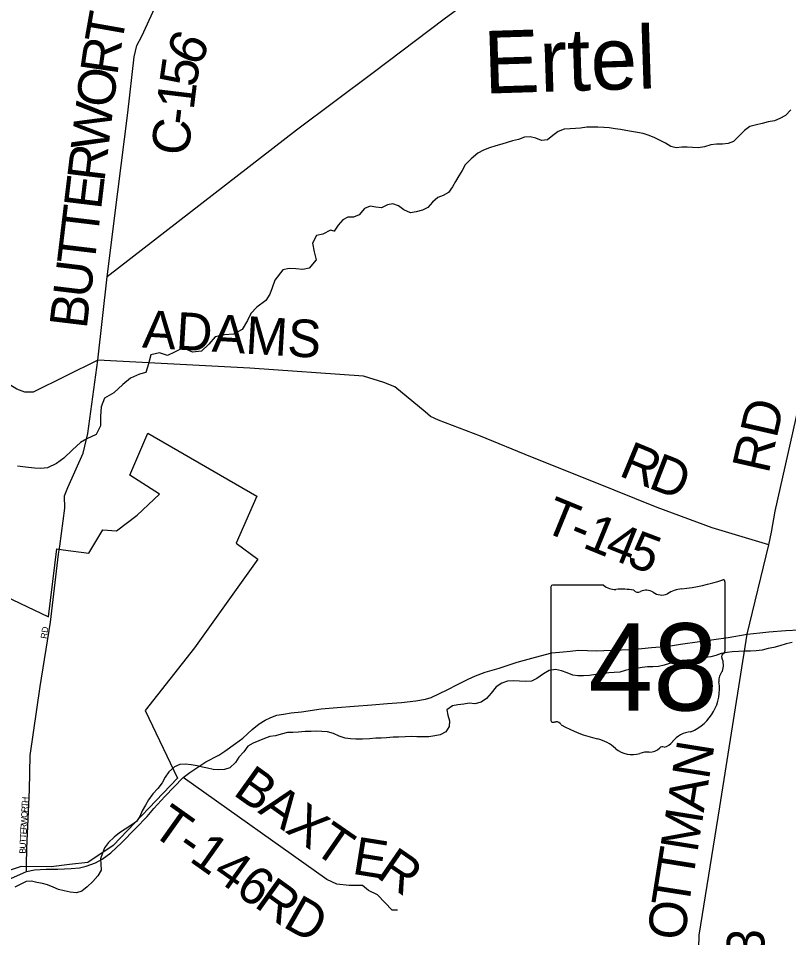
# Model space of a CAD drawing. Extents: x 0 to 1064, y 0 to 440.
# Drawn here: x 203.95 to 222.59, y 62.77 to 85.02 of the extents above; entities that cross this region are included whole.
import ezdxf

# ---------------------------------------------------------------- set-up
doc = ezdxf.new("R2010")
doc.units = 0
for name, color, linetype in [('GM_X_City_Street', 7, 'Continuous'), ('GM_X_City_Street_Text', 7, 'Continuous'), ('GM_X_Corporation', 7, 'Continuous'), ('GM_X_County_Road', 7, 'Continuous'), ('GM_X_County_Road_Text', 7, 'Continuous'), ('GM_X_Minor_River', 7, 'Continuous'), ('GM_X_Minor_River_Text', 7, 'Continuous'), ('GM_X_State_Location', 7, 'Continuous'), ('GM_X_State_Route', 7, 'Continuous'), ('GM_X_State_Shield', 7, 'Continuous'), ('GM_X_Township_Road', 7, 'Continuous'), ('GM_X_Township_Road_Text', 7, 'Continuous')]:
    doc.layers.add(name, color=color, linetype=linetype)

msp = doc.modelspace()

# ---------------------------------------------------------------- linework, layer by layer
at = {"layer": 'GM_X_City_Street'}
msp.add_lwpolyline([(204.15, 64.525), (204.154, 64.936), (204.221, 66.35), (204.236, 67.173), (204.474, 68.846), (204.731, 70.402), (204.924, 72.051), (204.949, 72.245)], dxfattribs=at)
at = {"layer": 'GM_X_Corporation'}
msp.add_lwpolyline([(201.73, 71.938), (204.68, 70.534), (204.882, 72.179), (205.035, 72.152), (205.655, 72.075), (205.997, 72.636), (206.326, 72.612), (206.826, 72.99), (207.362, 73.505), (206.643, 73.966), (207.082, 74.979), (209.718, 73.454), (209.218, 72.319), (209.742, 71.929), (208.211, 69.78), (207.021, 68.269), (207.798, 66.628), (206.247, 64.999), (205.631, 64.59), (205.188, 64.535), (204.746, 64.48), (204.02, 64.493), (203.4, 64.285)], dxfattribs=at)
at = {"layer": 'GM_X_County_Road'}
for points in [[(204.949, 72.245), (205.072, 73.161), (205.066, 73.464), (205.148, 73.663), (205.517, 74.495), (205.629, 74.973), (205.875, 76.746), (206.101, 78.761), (206.359, 80.822), (206.595, 82.732), (206.754, 84.084), (206.82, 84.362), (206.934, 84.591), (207.25, 85.272)], [(204.149, 64.367), (204.15, 64.525)]]:
    msp.add_lwpolyline(points, dxfattribs=at)
at = {"layer": 'GM_X_Minor_River'}
for points in [[(222.645, 82.806), (222.515, 82.669), (222.38, 82.592), (222.246, 82.539), (222.093, 82.511), (221.953, 82.477), (221.812, 82.443), (221.653, 82.397), (221.524, 82.308), (221.382, 82.164), (221.258, 82.039), (221.124, 81.986), (220.99, 81.976), (220.844, 81.972), (220.704, 81.956), (220.557, 81.91), (220.399, 81.888), (220.265, 81.89), (220.131, 81.898), (220.004, 81.901), (219.87, 81.884), (219.737, 81.917), (219.61, 81.998), (219.484, 82.061), (219.351, 82.124), (219.212, 82.18), (219.067, 82.231), (218.934, 82.252), (218.788, 82.278), (218.649, 82.305), (218.521, 82.325), (218.388, 82.346), (218.243, 82.366), (218.115, 82.374), (217.975, 82.382), (217.842, 82.385), (217.702, 82.381), (217.555, 82.359), (217.428, 82.355), (217.3, 82.345), (217.16, 82.335), (217.013, 82.282), (216.884, 82.181), (216.754, 82.08), (216.608, 82.064), (216.469, 82.121), (216.336, 82.153), (216.196, 82.143), (216.049, 82.085), (215.909, 82.051), (215.781, 82.016), (215.646, 81.976), (215.5, 81.93), (215.353, 81.883), (215.206, 81.831), (215.071, 81.754), (214.905, 81.617), (214.762, 81.474), (214.687, 81.335), (214.612, 81.203), (214.531, 81.07), (214.456, 80.938), (214.356, 80.8), (214.227, 80.729), (214.099, 80.682), (213.969, 80.569), (213.858, 80.443), (213.729, 80.378), (213.576, 80.332), (213.436, 80.31), (213.279, 80.385), (213.147, 80.479), (213.014, 80.529), (212.88, 80.501), (212.739, 80.436), (212.599, 80.445), (212.466, 80.471), (212.325, 80.413), (212.195, 80.263), (212.06, 80.204), (211.926, 80.206), (211.798, 80.142), (211.686, 80.01), (211.593, 79.865), (211.589, 79.863)], [(211.593, 79.865), (211.506, 79.891), (211.321, 79.798), (211.162, 79.76), (211.066, 79.574), (211.109, 79.366), (211.159, 79.17), (210.99, 78.974), (210.831, 78.936), (210.661, 78.952), (210.503, 78.968), (210.35, 78.929), (210.155, 78.679), (210.089, 78.499), (210.031, 78.342), (209.935, 78.186), (209.724, 78.028), (209.574, 77.874), (209.491, 77.705), (209.364, 77.49), (209.154, 77.374), (208.935, 77.355), (208.708, 77.312), (208.558, 77.133), (208.383, 76.962), (208.164, 76.943), (207.935, 77.04), (207.725, 76.942), (207.559, 76.855), (207.366, 76.92), (207.152, 76.871), (207.098, 76.66), (207.031, 76.443), (206.878, 76.404), (206.663, 76.312), (206.476, 76.153), (206.258, 75.952), (206.036, 75.823), (205.951, 75.613), (205.939, 75.382), (205.934, 75.158), (205.831, 74.948), (205.609, 74.838), (205.449, 74.751), (205.262, 74.573), (205.05, 74.372), (204.876, 74.243), (204.654, 74.139), (204.496, 74.124), (204.338, 74.135), (204.119, 74.158), (203.925, 74.181)], [(222.678, 69.912), (222.532, 69.878), (222.373, 69.832), (222.232, 69.792), (222.098, 69.769), (221.946, 69.729), (221.805, 69.713), (221.665, 69.703), (221.532, 69.706), (221.38, 69.696), (221.227, 69.686), (221.1, 69.67), (220.959, 69.648), (220.831, 69.601), (220.703, 69.567), (220.575, 69.545), (220.434, 69.516), (220.264, 69.495), (220.136, 69.485), (220.002, 69.475), (219.856, 69.453), (219.709, 69.4), (219.581, 69.36), (219.44, 69.332), (219.3, 69.322), (219.173, 69.324), (219.045, 69.308), (218.898, 69.286), (218.771, 69.269), (218.636, 69.235), (218.502, 69.195), (218.368, 69.185), (218.24, 69.175), (218.076, 69.153), (217.923, 69.137), (217.771, 69.115), (217.625, 69.105), (217.491, 69.102), (217.364, 69.122), (217.231, 69.179), (217.092, 69.223), (216.946, 69.256), (216.794, 69.234), (216.659, 69.157), (216.499, 69.044), (216.364, 68.98), (216.224, 68.97), (216.079, 68.978), (215.921, 68.987), (215.787, 68.977), (215.652, 68.924), (215.511, 68.835), (215.387, 68.685), (215.275, 68.554), (215.146, 68.464), (214.999, 68.43), (214.86, 68.445), (214.726, 68.423), (214.585, 68.4), (214.457, 68.378), (214.322, 68.283), (214.344, 68.155), (214.384, 68.015), (214.376, 67.875), (214.295, 67.749), (214.154, 67.678), (214.026, 67.656)], [(211.033, 67.759), (211.024, 67.759), (210.891, 67.755), (210.732, 67.745), (210.592, 67.735), (210.465, 67.731), (210.312, 67.697), (210.172, 67.657), (210.037, 67.634), (209.909, 67.588), (209.768, 67.529), (209.634, 67.477), (209.505, 67.406), (209.405, 67.268), (209.287, 67.136), (209.2, 67.004), (209.07, 66.878), (208.936, 66.838), (208.802, 66.828), (208.662, 66.836), (208.529, 66.869), (208.402, 66.895), (208.275, 66.927), (208.135, 66.954), (207.996, 66.968), (207.856, 66.958), (207.727, 66.906), (207.591, 66.78), (207.498, 66.654), (207.429, 66.516), (207.323, 66.377), (207.2, 66.252), (207.1, 66.108), (207.025, 65.975), (206.943, 65.837), (206.892, 65.704), (206.805, 65.578), (206.67, 65.483), (206.535, 65.394), (206.399, 65.305), (206.27, 65.197), (206.128, 65.072), (206.035, 64.946), (205.984, 64.813), (205.939, 64.68), (205.949, 64.546), (205.953, 64.4), (205.871, 64.262), (205.753, 64.124), (205.618, 63.999), (205.482, 63.897), (205.354, 63.857), (205.202, 63.871), (205.057, 63.898), (204.923, 63.931), (204.791, 63.987), (204.658, 64.044), (204.531, 64.077), (204.397, 64.103), (204.27, 64.135), (204.136, 64.125), (203.989, 64.055), (203.86, 63.99)], [(214.026, 67.656), (213.879, 67.628), (213.74, 67.63), (213.594, 67.632), (213.454, 67.635), (213.308, 67.631), (213.15, 67.621), (213.016, 67.617), (212.858, 67.602), (212.73, 67.598), (212.602, 67.594), (212.45, 67.584), (212.28, 67.574), (212.116, 67.571), (211.988, 67.579), (211.855, 67.599), (211.716, 67.644), (211.577, 67.707), (211.432, 67.746), (211.292, 67.76), (211.152, 67.763), (211.033, 67.759)]]:
    msp.add_lwpolyline(points, dxfattribs=at)
at = {"layer": 'GM_X_State_Route'}
for points in [[(208.894, 67.246), (208.948, 67.28), (209.204, 67.467), (209.378, 67.599), (209.607, 67.805), (209.777, 67.944), (209.921, 68.031), (210.06, 68.096), (210.204, 68.151), (210.364, 68.181), (210.548, 68.211), (210.804, 68.235), (211.277, 68.303), (211.662, 68.337), (212.078, 68.372), (212.501, 68.405), (212.882, 68.435), (213.225, 68.459), (213.566, 68.504), (213.805, 68.544), (213.939, 68.584), (214.128, 68.666), (214.342, 68.773), (214.558, 68.887), (214.835, 69.027), (215.011, 69.104), (215.245, 69.191), (215.586, 69.29), (216.024, 69.435), (216.462, 69.559), (216.855, 69.659), (217.133, 69.684), (217.303, 69.703), (217.507, 69.723), (217.94, 69.708), (218.298, 69.728), (218.8, 69.743), (219.268, 69.788), (219.681, 69.823), (219.97, 69.873), (220.432, 69.937), (221.129, 70.032), (221.584, 70.111), (221.895, 70.146)], [(221.895, 70.146), (222.114, 70.171), (222.518, 70.206), (222.851, 70.216)], [(203.692, 64.164), (204.149, 64.367), (204.343, 64.407), (204.626, 64.426), (204.905, 64.429), (205.229, 64.444), (205.43, 64.459), (205.587, 64.499), (205.813, 64.583), (205.975, 64.668), (206.184, 64.824), (206.443, 65.061), (206.788, 65.409), (207.067, 65.703), (207.231, 65.897), (207.495, 66.188), (207.938, 66.646), (208.102, 66.768), (208.49, 67.021), (208.804, 67.188), (208.894, 67.246)]]:
    msp.add_lwpolyline(points, dxfattribs=at)
at = {"layer": 'GM_X_State_Shield'}
for p, q in [((216.831, 71.242), (216.831, 68.04)), ((218.108, 71.297), (216.872, 71.297)), ((221.05, 69.702), (221.05, 71.377)), ((221.049, 69.702), (221.05, 69.702))]:
    msp.add_line(p, q, dxfattribs=at)
for centre, radius, start, end in [((219.547, 75.663), 4.474, 275.8445, 288.9065), ((221.003, 71.384), 0.047, 351.8621, 97.738), ((216.879, 71.249), 0.0489, 98.1301, 188.1301), ((218.402, 71.669), 0.474, 231.6195, 271.1119), ((218.559, 69.5), 1.702, 80.4867, 94.9883), ((220.117, 70.319), 0.9, 97.3462, 120.7689), ((218.946, 71.266), 0.137, 219.7921, 297.1024), ((219.146, 70.896), 0.284, 54.4667, 119.1411), ((219.513, 71.403), 0.342, 233.8562, 294.8282), ((221.039, 69.579), 0.0727, 107.944, 210.337), ((220.999, 69.695), 0.0503, 289.6038, 7.7341), ((220.576, 69.367), 0.436, 340.033, 23.6496), ((221.218, 69.001), 0.317, 136.8065, 186.9296), ((219.797, 68.788), 1.119, 292.3089, 8.9858), ((216.88, 68.033), 0.0493, 171.9584, 258.3066), ((216.887, 68.361), 0.376, 267.339, 280.6039), ((216.964, 67.856), 0.136, 29.7484, 93.2717), ((218.677, 70.732), 3.231, 240.4129, 257.1985), ((220.269, 67.141), 0.613, 94.4031, 142.5768), ((217.714, 66.602), 1.011, 47.1842, 75.836), ((219.493, 67.73), 0.362, 282.8732, 323.2771), ((218.807, 67.84), 0.641, 230.7004, 286.2918), ((219.178, 66.733), 0.527, 85.6951, 111.2099), ((219.225, 67.6), 0.342, 268.777, 315.5493), ((219.534, 67.29), 0.0962, 65.7517, 132.6484)]:
    msp.add_arc(centre, radius, start, end, dxfattribs=at)
at = {"layer": 'GM_X_Township_Road'}
for points in [[(222.171, 72.586), (222.266, 73.091), (223.264, 77.53), (223.365, 77.916), (224.549, 80.175), (224.771, 80.759), (225.162, 82.306), (225.734, 84.566), (226.09, 85.395), (226.206, 85.636), (226.333, 85.852), (226.734, 86.279), (226.976, 86.751), (227.402, 87.688), (227.775, 88.482), (228.291, 89.653), (228.585, 90.64), (228.902, 92.053), (229.253, 93.162), (229.655, 94.135), (231.335, 97.797)], [(221.787, 87.26), (221.787, 87.107), (221.009, 86.989), (219.201, 86.881), (216.676, 86.714), (216.452, 86.642), (216.112, 86.396), (215.338, 85.796), (214.253, 85), (212.539, 83.698), (210.68, 82.316), (206.101, 78.761)], [(205.875, 76.746), (204.306, 75.971), (204.102, 75.971), (203.91, 76.047), (203.293, 76.425), (200.531, 78.313), (200.292, 78.441), (200.088, 78.406), (199.886, 78.147), (198.408, 76.087), (197.228, 76.804), (197.035, 76.88), (196.773, 76.816), (196.65, 76.738), (196.592, 76.623), (195.325, 74.834), (195.296, 74.789)], [(222.113, 72.275), (220.74, 72.688), (219.41, 73.182), (217.828, 73.814), (216.35, 74.408), (215.134, 74.907), (214.117, 75.297), (213.923, 75.382), (213.79, 75.491), (213.063, 76.1), (212.792, 76.204), (212.298, 76.361), (209.547, 76.551), (205.875, 76.746)], [(221.584, 70.111), (221.584, 70.111), (222.113, 72.275), (222.171, 72.586)], [(220.322, 58.43), (220.348, 59.863), (220.377, 60.968), (220.426, 62.825), (220.928, 65.934), (221.584, 70.111)], [(213.125, 63.434), (212.996, 63.434), (212.643, 63.807), (212.419, 63.911), (212.274, 64.031), (211.951, 64.031), (211.657, 64.066), (211.414, 64.175), (207.938, 66.646)]]:
    msp.add_lwpolyline(points, dxfattribs=at)

# ---------------------------------------------------------------- texts
at = {"layer": 'GM_X_City_Street_Text'}
for s, height, rotation, p in [('RD', 0.1515, 81.0327, (204.635, 69.994)), ('H', 0.152, 87.0263, (204.185, 66.027)), ('R', 0.152, 87.0115, (204.173, 65.8)), ('T', 0.152, 87.0375, (204.179, 65.92)), ('W', 0.152, 87.026, (204.157, 65.494)), ('O', 0.152, 87.0044, (204.166, 65.667)), ('R', 0.152, 87.0115, (204.15, 65.374)), ('T', 0.152, 87.0202, (204.139, 65.161)), ('E', 0.152, 87.0375, (204.145, 65.268)), ('U', 0.152, 87.7041, (204.129, 64.922)), ('T', 0.152, 87.0475, (204.134, 65.054)), ('B', 0.152, 89.5871, (204.128, 64.803))]:
    msp.add_text(s, height=height, rotation=rotation, dxfattribs=at).set_placement(p)
at = {"layer": 'GM_X_County_Road_Text'}
for s, rotation, p in [('T', 79.9761, (206.448, 84.353)), ('6', 64.4892, (208.315, 83.816)), ('R', 81.6767, (206.342, 83.621)), ('5', 81.9332, (208.257, 83.332)), ('O', 83.0141, (206.245, 82.833)), ('1', 83.1299, (208.191, 82.781)), ('W', 83.1306, (206.119, 81.787)), ('-', 83.1538, (208.147, 82.41)), ('C', 83.1732, (208.058, 81.669)), ('R', 83.1328, (206.03, 81.046)), ('E', 83.1264, (205.948, 80.371)), ('T', 83.1317, (205.867, 79.696)), ('T', 83.1317, (205.786, 79.021)), ('U', 83.128, (205.69, 78.226)), ('B', 83.1301, (205.601, 77.485))]:
    msp.add_text(s, height=0.909, rotation=rotation, dxfattribs=at).set_placement(p)
at = {"layer": 'GM_X_Minor_River_Text'}
msp.add_text('Ertel', height=1.5151, rotation=1.8077, dxfattribs=at).set_placement((215.229, 83.195))
at = {"layer": 'GM_X_State_Location'}
for s in ['s', 'r']:
    msp.add_text(s, height=0.00303, dxfattribs=at).set_placement((218.893, 69.428))
msp.add_text('48', height=0.00303, rotation=0, dxfattribs=at).set_placement((218.13, 69.208))
at = {"layer": 'GM_X_State_Shield'}
msp.add_text('48', height=2.1094, dxfattribs=at).set_placement((217.741, 68.266))
at = {"layer": 'GM_X_Township_Road_Text'}
for s, height, rotation, p in [('ADAMS', 0.9091, 356.5782, (206.935, 77.054)), ('RD', 0.9091, 77.1539, (222.101, 73.976)), ('R', 0.909, 337.5456, (218.453, 73.96)), ('D', 0.909, 338.8847, (219.165, 73.666)), ('T', 0.909, 337.7283, (216.598, 72.623)), ('1', 0.909, 337.826, (217.575, 72.223)), ('-', 0.909, 337.7407, (217.228, 72.365)), ('4', 0.909, 338.1218, (218.098, 72.01)), ('5', 0.909, 339.371, (218.638, 71.794)), ('N', 0.909, 80.8909, (220.661, 66.573)), ('B', 0.909, 324.3752, (209.118, 66.245)), ('A', 0.909, 80.8909, (220.534, 65.783)), ('A', 0.909, 324.3766, (209.725, 65.81)), ('T-146', 0.9091, 324.5932, (207.122, 65.304)), ('X', 0.909, 324.3792, (210.375, 65.344)), ('M', 0.909, 80.8883, (220.378, 64.809)), ('T', 0.909, 325.3136, (211.039, 64.869)), ('E', 0.909, 350.8643, (212.005, 64.318)), ('T', 0.909, 80.8892, (220.27, 64.138)), ('R', 0.909, 325.4342, (212.579, 64.249)), ('T', 0.909, 81.028, (220.164, 63.466)), ('R', 0.909, 324.2886, (209.628, 63.537)), ('D', 0.909, 330.3529, (210.321, 63.045)), ('O', 0.909, 83.6011, (220.077, 62.682)), ('T-143', 0.9091, 88.5956, (221.934, 59.793))]:
    msp.add_text(s, height=height, rotation=rotation, dxfattribs=at).set_placement(p)

doc.saveas('drawing.dxf')
